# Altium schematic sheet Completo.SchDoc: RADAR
size A4; Author: Almela; Revision: 1.2; SheetNumber: 1; SheetTotal: 7
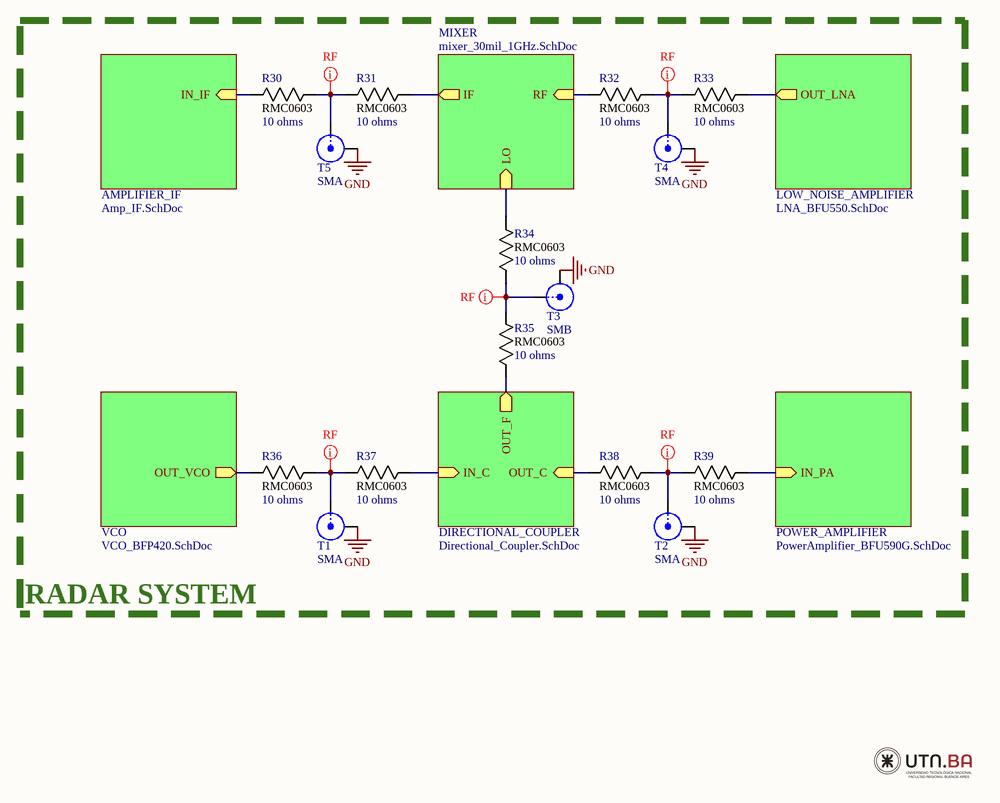
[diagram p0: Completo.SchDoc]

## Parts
R30  value 10 ohms  footprint: RMC0603  [RESC1508X55N]  (hidden comment: Resistor)
R31  value 10 ohms  footprint: RMC0603  [RESC1508X55N]  (hidden comment: Resistor)
R32  value 10 ohms  footprint: RMC0603  [RESC1508X55N]  (hidden comment: Resistor)
R33  value 10 ohms  footprint: RMC0603  [RESC1508X55N]  (hidden comment: Resistor)
R34  value 10 ohms  footprint: RMC0603  [RESC1508X55N]  (hidden comment: Resistor)
R35  value 10 ohms  footprint: RMC0603  [RESC1508X55N]  (hidden comment: Resistor)
R36  value 10 ohms  footprint: RMC0603  [RESC1508X55N]  (hidden comment: Resistor)
R37  value 10 ohms  footprint: RMC0603  [RESC1508X55N]  (hidden comment: Resistor)
R38  value 10 ohms  footprint: RMC0603  [RESC1508X55N]  (hidden comment: Resistor)
R39  value 10 ohms  footprint: RMC0603  [RESC1508X55N]  (hidden comment: Resistor)
T1  SMA  [SMA-142-0701-851]
T2  SMA  [SMA-142-0701-851]
T3  SMB  [SMB_V-RJ45]
T4  SMA  [SMA-142-0701-851]
T5  SMA  [SMA-142-0701-851]

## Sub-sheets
AMPLIFIER_IF = Amp_IF.SchDoc: IN_IF (in)
DIRECTIONAL_COUPLER = Directional_Coupler.SchDoc: IN_C (in), OUT_F (out), OUT_C (in)
LOW_NOISE_AMPLIFIER = LNA_BFU550.SchDoc: OUT_LNA (out)
MIXER = mixer_30mil_1GHz.SchDoc: IF (out), RF (in), LO (in)
POWER_AMPLIFIER = PowerAmplifier_BFU590G.SchDoc: IN_PA (in)
VCO = VCO_BFP420.SchDoc: OUT_VCO (out)

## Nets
GND: T1.2(Y) T2.2(Y) T3.2(Y) T4.2(Y) T5.2(Y)
NetR30_1: R30.1 ; sheet AMPLIFIER_IF/IN_IF
NetR30_2: R30.2 R31.1 T5.1(X)
NetR31_2: R31.2 ; sheet MIXER/IF
NetR32_1: R32.1 ; sheet MIXER/RF
NetR32_2: R32.2 R33.1 T4.1(X)
NetR33_2: R33.2 ; sheet LOW_NOISE_AMPLIFIER/OUT_LNA
NetR34_1: R34.1 R35.2 T3.1(X)
NetR34_2: R34.2 ; sheet MIXER/LO
NetR35_1: R35.1 ; sheet DIRECTIONAL_COUPLER/OUT_F
NetR36_1: R36.1 ; sheet VCO/OUT_VCO
NetR36_2: R36.2 R37.1 T1.1(X)
NetR37_2: R37.2 ; sheet DIRECTIONAL_COUPLER/IN_C
NetR38_1: R38.1 ; sheet DIRECTIONAL_COUPLER/OUT_C
NetR38_2: R38.2 R39.1 T2.1(X)
NetR39_2: R39.2 ; sheet POWER_AMPLIFIER/IN_PA

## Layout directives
net class RF50R: NetR30_2, NetR32_2, NetR34_1, NetR36_2, NetR38_2

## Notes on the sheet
- RADAR SYSTEM

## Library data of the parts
R30-R39 = Resistor: Resistor RMC0603; Mfr_Name: Stackpole International
T1-T5 = SMB: SMB Straight Connector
